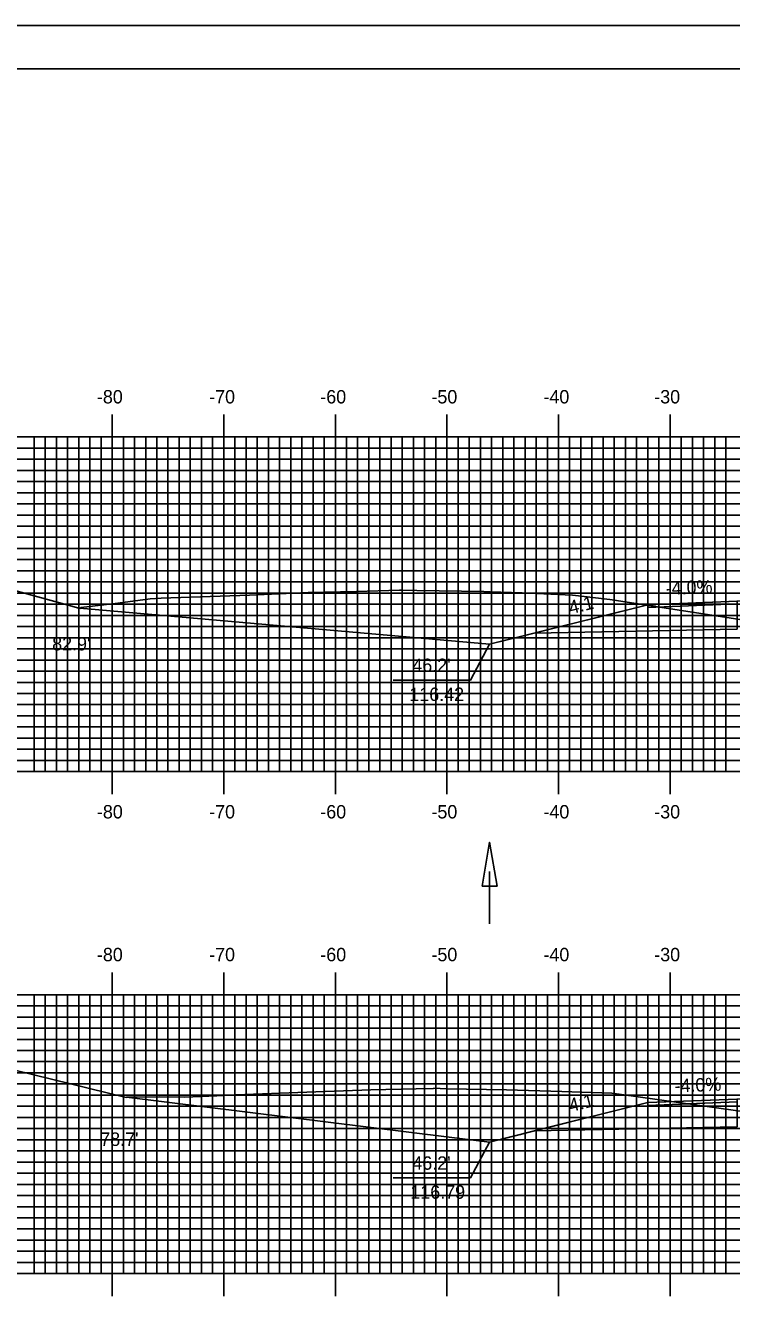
# Model space of a CAD drawing. Extents: x 854287 to 854631, y 366605 to 366825.
# Drawn here: x 854365.3 to 854428.5, y 366710.6 to 366824.9 of the extents above; entities that cross this region are included whole.
import ezdxf

# ---------------------------------------------------------------- set-up
doc = ezdxf.new("R2010")
doc.units = 0
for name, color, linetype in [('ANNOTATION', 7, 'Continuous'), ('BORDER', 7, 'Continuous'), ('D_Drainage_Ditch_Line', 7, 'Continuous'), ('D_Drainage_Underdrain', 7, 'Continuous'), ('D_Roadway_Centerline', 7, 'Continuous'), ('D_Roadway_Edge_Shoulder', 7, 'Continuous'), ('D_Roadway_SlopeLines', 7, 'Continuous'), ('D_Roadway_SubGrade', 7, 'Continuous'), ('D_Text_Standard', 7, 'Continuous'), ('H_V ANNOTATION', 7, 'Continuous'), ('M_Roadway_Centerline', 7, 'Continuous'), ('MAJOR', 7, 'Continuous'), ('MINOR', 7, 'Continuous'), ('PLOT BOUNDARY', 7, 'Continuous'), ('S_Roadway_Centerline', 7, 'Continuous')]:
    doc.layers.add(name, color=color, linetype=linetype)

msp = doc.modelspace()

# ---------------------------------------------------------------- linework, layer by layer
at = {"layer": 'ANNOTATION'}
for points in [[(854410.87, 366770.48), (854406.87, 366769.48), (854370.14, 366772.7)], [(854398.21, 366766.27), (854405.14, 366766.27), (854406.87, 366769.48)], [(854398.21, 366721.64), (854405.14, 366721.64), (854406.87, 366724.85)]]:
    msp.add_lwpolyline(points, dxfattribs=at)
at = {"layer": 'BORDER'}
msp.add_lwpolyline([(854303.44, 366611.06), (854623.44, 366611.06), (854623.44, 366821.06), (854303.44, 366821.06)], close=True, dxfattribs=at)
at = {"layer": 'D_Drainage_Ditch_Line'}
msp.add_line((854406.87, 366749.11), (854406.87, 366744.41), dxfattribs=at)
msp.add_lwpolyline([(854407.53, 366747.8), (854406.21, 366747.8), (854406.87, 366751.73)], close=True, dxfattribs=at)
at = {"layer": 'D_Drainage_Underdrain'}
msp.add_lwpolyline([(854410.87, 366725.85), (854406.87, 366724.85), (854374.32, 366728.87)], dxfattribs=at)
at = {"layer": 'D_Roadway_Centerline'}
for points in [[(854370.14, 366772.7), (854370.15, 366772.7), (854406.87, 366769.48), (854410.14, 366770.29), (854410.15, 366770.29), (854421.04, 366773.02), (854421.05, 366773.02), (854423.89, 366773.13), (854429.04, 366773.34), (854429.04, 366773.34), (854441.04, 366773.58), (854441.04, 366773.58), (854449.37, 366773.75), (854453.04, 366773.82), (854454.84, 366773.75), (854457.04, 366773.66), (854463.48, 366772.96), (854463.48, 366772.96)], [(854374.32, 366728.87), (854406.87, 366724.85), (854409.62, 366725.54), (854410.14, 366725.67), (854421.04, 366728.39), (854422.63, 366728.46), (854429.04, 366728.71), (854429.04, 366728.71), (854429.05, 366728.71), (854441.04, 366728.95), (854447.09, 366729.07), (854453.04, 366729.19), (854453.58, 366729.17), (854457.04, 366729.03), (854464.66, 366728.25)]]:
    msp.add_lwpolyline(points, dxfattribs=at)
at = {"layer": 'D_Roadway_Edge_Shoulder'}
for points in [[(854429.04, 366773.34), (854421.04, 366773.02), (854421.04, 366772.77), (854429.04, 366773.09)], [(854429.04, 366728.71), (854421.04, 366728.39), (854421.04, 366728.14), (854429.04, 366728.46)]]:
    msp.add_lwpolyline(points, close=True, dxfattribs=at)
at = {"layer": 'D_Roadway_SlopeLines'}
for p, q in [((854406.87, 366769.48), (854370.14, 366772.7)), ((854421.04, 366773.02), (854406.87, 366769.48)), ((854406.87, 366724.85), (854374.32, 366728.87)), ((854421.04, 366728.39), (854406.87, 366724.85))]:
    msp.add_line(p, q, dxfattribs=at)
at = {"layer": 'D_Roadway_SubGrade'}
for points in [[(854429.04, 366772.67), (854429.04, 366773.09), (854421.04, 366772.77), (854421.04, 366773.02), (854410.87, 366770.48), (854429.04, 366770.84)], [(854429.04, 366728.05), (854429.04, 366728.46), (854421.04, 366728.14), (854421.04, 366728.39), (854410.87, 366725.85), (854429.04, 366726.21)]]:
    msp.add_lwpolyline(points, close=True, dxfattribs=at)
at = {"layer": 'MAJOR'}
for p, q in [((854373.04, 366790.06), (854373.04, 366788.06)), ((854383.04, 366790.06), (854383.04, 366788.06)), ((854393.04, 366790.06), (854393.04, 366788.06)), ((854403.04, 366790.06), (854403.04, 366788.06)), ((854413.04, 366790.06), (854413.04, 366788.06)), ((854423.04, 366790.06), (854423.04, 366788.06)), ((854313.04, 366788.06), (854593.04, 366788.06)), ((854313.04, 366788.06), (854593.04, 366788.06)), ((854373.04, 366758.06), (854373.04, 366788.06)), ((854383.04, 366758.06), (854383.04, 366788.06)), ((854393.04, 366758.06), (854393.04, 366788.06)), ((854403.04, 366758.06), (854403.04, 366788.06)), ((854413.04, 366758.06), (854413.04, 366788.06)), ((854423.04, 366758.06), (854423.04, 366788.06)), ((854313.04, 366783.06), (854593.04, 366783.06)), ((854313.04, 366778.06), (854593.04, 366778.06)), ((854313.04, 366773.06), (854593.04, 366773.06)), ((854313.04, 366768.06), (854593.04, 366768.06)), ((854313.04, 366763.06), (854593.04, 366763.06)), ((854313.04, 366758.06), (854593.04, 366758.06)), ((854313.04, 366758.06), (854593.04, 366758.06)), ((854373.04, 366756.05), (854373.04, 366758.06)), ((854383.04, 366756.05), (854383.04, 366758.06)), ((854393.04, 366756.05), (854393.04, 366758.06)), ((854403.04, 366756.05), (854403.04, 366758.06)), ((854413.04, 366756.05), (854413.04, 366758.06)), ((854423.04, 366756.05), (854423.04, 366758.06)), ((854373.04, 366740.06), (854373.04, 366738.06)), ((854383.04, 366740.06), (854383.04, 366738.06)), ((854393.04, 366740.06), (854393.04, 366738.06)), ((854403.04, 366740.06), (854403.04, 366738.06)), ((854413.04, 366740.06), (854413.04, 366738.06)), ((854423.04, 366740.06), (854423.04, 366738.06)), ((854313.04, 366738.06), (854593.04, 366738.06)), ((854313.04, 366738.06), (854593.04, 366738.06)), ((854373.04, 366713.06), (854373.04, 366738.06)), ((854383.04, 366713.06), (854383.04, 366738.06)), ((854393.04, 366713.06), (854393.04, 366738.06)), ((854403.04, 366713.06), (854403.04, 366738.06)), ((854413.04, 366713.06), (854413.04, 366738.06)), ((854423.04, 366713.06), (854423.04, 366738.06)), ((854313.04, 366733.06), (854593.04, 366733.06)), ((854313.04, 366728.06), (854593.04, 366728.06)), ((854313.04, 366723.06), (854593.04, 366723.06)), ((854313.04, 366718.06), (854593.04, 366718.06)), ((854313.04, 366713.06), (854593.04, 366713.06)), ((854313.04, 366713.06), (854593.04, 366713.06)), ((854373.04, 366711.05), (854373.04, 366713.06)), ((854383.04, 366711.05), (854383.04, 366713.06)), ((854393.04, 366711.05), (854393.04, 366713.06)), ((854403.04, 366711.05), (854403.04, 366713.06)), ((854413.04, 366711.05), (854413.04, 366713.06)), ((854423.04, 366711.05), (854423.04, 366713.06))]:
    msp.add_line(p, q, dxfattribs=at)
at = {"layer": 'MINOR'}
for p, q in [((854366.04, 366758.06), (854366.04, 366788.06)), ((854367.04, 366758.06), (854367.04, 366788.06)), ((854368.04, 366758.06), (854368.04, 366788.06)), ((854369.04, 366758.06), (854369.04, 366788.06)), ((854370.04, 366758.06), (854370.04, 366788.06)), ((854371.04, 366758.06), (854371.04, 366788.06)), ((854372.04, 366758.06), (854372.04, 366788.06)), ((854374.04, 366758.06), (854374.04, 366788.06)), ((854375.04, 366758.06), (854375.04, 366788.06)), ((854376.04, 366758.06), (854376.04, 366788.06)), ((854377.04, 366758.06), (854377.04, 366788.06)), ((854378.04, 366758.06), (854378.04, 366788.06)), ((854379.04, 366758.06), (854379.04, 366788.06)), ((854380.04, 366758.06), (854380.04, 366788.06)), ((854381.04, 366758.06), (854381.04, 366788.06)), ((854382.04, 366758.06), (854382.04, 366788.06)), ((854384.04, 366758.06), (854384.04, 366788.06)), ((854385.04, 366758.06), (854385.04, 366788.06)), ((854386.04, 366758.06), (854386.04, 366788.06)), ((854387.04, 366758.06), (854387.04, 366788.06)), ((854388.04, 366758.06), (854388.04, 366788.06)), ((854389.04, 366758.06), (854389.04, 366788.06)), ((854390.04, 366758.06), (854390.04, 366788.06)), ((854391.04, 366758.06), (854391.04, 366788.06)), ((854392.04, 366758.06), (854392.04, 366788.06)), ((854394.04, 366758.06), (854394.04, 366788.06)), ((854395.04, 366758.06), (854395.04, 366788.06)), ((854396.04, 366758.06), (854396.04, 366788.06)), ((854397.04, 366758.06), (854397.04, 366788.06)), ((854398.04, 366758.06), (854398.04, 366788.06)), ((854399.04, 366758.06), (854399.04, 366788.06)), ((854400.04, 366758.06), (854400.04, 366788.06)), ((854401.04, 366758.06), (854401.04, 366788.06)), ((854402.04, 366758.06), (854402.04, 366788.06)), ((854404.04, 366758.06), (854404.04, 366788.06)), ((854405.04, 366758.06), (854405.04, 366788.06)), ((854406.04, 366758.06), (854406.04, 366788.06)), ((854407.04, 366758.06), (854407.04, 366788.06)), ((854408.04, 366758.06), (854408.04, 366788.06)), ((854409.04, 366758.06), (854409.04, 366788.06)), ((854410.04, 366758.06), (854410.04, 366788.06)), ((854411.04, 366758.06), (854411.04, 366788.06)), ((854412.04, 366758.06), (854412.04, 366788.06)), ((854414.04, 366758.06), (854414.04, 366788.06)), ((854415.04, 366758.06), (854415.04, 366788.06)), ((854416.04, 366758.06), (854416.04, 366788.06)), ((854417.04, 366758.06), (854417.04, 366788.06)), ((854418.04, 366758.06), (854418.04, 366788.06)), ((854419.04, 366758.06), (854419.04, 366788.06)), ((854420.04, 366758.06), (854420.04, 366788.06)), ((854421.04, 366758.06), (854421.04, 366788.06)), ((854422.04, 366758.06), (854422.04, 366788.06)), ((854424.04, 366758.06), (854424.04, 366788.06)), ((854425.04, 366758.06), (854425.04, 366788.06)), ((854426.04, 366758.06), (854426.04, 366788.06)), ((854427.04, 366758.06), (854427.04, 366788.06)), ((854428.04, 366758.06), (854428.04, 366788.06)), ((854313.04, 366787.06), (854593.04, 366787.06)), ((854313.04, 366786.06), (854593.04, 366786.06)), ((854313.04, 366785.06), (854593.04, 366785.06)), ((854313.04, 366784.06), (854593.04, 366784.06)), ((854313.04, 366782.06), (854593.04, 366782.06)), ((854313.04, 366781.06), (854593.04, 366781.06)), ((854313.04, 366780.06), (854593.04, 366780.06)), ((854313.04, 366779.06), (854593.04, 366779.06)), ((854313.04, 366777.06), (854593.04, 366777.06)), ((854313.04, 366776.06), (854593.04, 366776.06)), ((854313.04, 366775.06), (854593.04, 366775.06)), ((854313.04, 366774.06), (854593.04, 366774.06)), ((854313.04, 366772.06), (854593.04, 366772.06)), ((854313.04, 366771.06), (854593.04, 366771.06)), ((854313.04, 366770.06), (854593.04, 366770.06)), ((854313.04, 366769.06), (854593.04, 366769.06)), ((854313.04, 366767.06), (854593.04, 366767.06)), ((854313.04, 366766.06), (854593.04, 366766.06)), ((854313.04, 366765.06), (854593.04, 366765.06)), ((854313.04, 366764.06), (854593.04, 366764.06)), ((854313.04, 366762.06), (854593.04, 366762.06)), ((854313.04, 366761.06), (854593.04, 366761.06)), ((854313.04, 366760.06), (854593.04, 366760.06)), ((854313.04, 366759.06), (854593.04, 366759.06)), ((854313.04, 366737.06), (854593.04, 366737.06)), ((854366.04, 366713.06), (854366.04, 366738.06)), ((854367.04, 366713.06), (854367.04, 366738.06)), ((854368.04, 366713.06), (854368.04, 366738.06)), ((854369.04, 366713.06), (854369.04, 366738.06)), ((854370.04, 366713.06), (854370.04, 366738.06)), ((854371.04, 366713.06), (854371.04, 366738.06)), ((854372.04, 366713.06), (854372.04, 366738.06)), ((854374.04, 366713.06), (854374.04, 366738.06)), ((854375.04, 366713.06), (854375.04, 366738.06)), ((854376.04, 366713.06), (854376.04, 366738.06)), ((854377.04, 366713.06), (854377.04, 366738.06)), ((854378.04, 366713.06), (854378.04, 366738.06)), ((854379.04, 366713.06), (854379.04, 366738.06)), ((854380.04, 366713.06), (854380.04, 366738.06)), ((854381.04, 366713.06), (854381.04, 366738.06)), ((854382.04, 366713.06), (854382.04, 366738.06)), ((854384.04, 366713.06), (854384.04, 366738.06)), ((854385.04, 366713.06), (854385.04, 366738.06)), ((854386.04, 366713.06), (854386.04, 366738.06)), ((854387.04, 366713.06), (854387.04, 366738.06)), ((854388.04, 366713.06), (854388.04, 366738.06)), ((854389.04, 366713.06), (854389.04, 366738.06)), ((854390.04, 366713.06), (854390.04, 366738.06)), ((854391.04, 366713.06), (854391.04, 366738.06)), ((854392.04, 366713.06), (854392.04, 366738.06)), ((854394.04, 366713.06), (854394.04, 366738.06)), ((854395.04, 366713.06), (854395.04, 366738.06)), ((854396.04, 366713.06), (854396.04, 366738.06)), ((854397.04, 366713.06), (854397.04, 366738.06)), ((854398.04, 366713.06), (854398.04, 366738.06)), ((854399.04, 366713.06), (854399.04, 366738.06)), ((854400.04, 366713.06), (854400.04, 366738.06)), ((854401.04, 366713.06), (854401.04, 366738.06)), ((854402.04, 366713.06), (854402.04, 366738.06)), ((854404.04, 366713.06), (854404.04, 366738.06)), ((854405.04, 366713.06), (854405.04, 366738.06)), ((854406.04, 366713.06), (854406.04, 366738.06)), ((854407.04, 366713.06), (854407.04, 366738.06)), ((854408.04, 366713.06), (854408.04, 366738.06)), ((854409.04, 366713.06), (854409.04, 366738.06)), ((854410.04, 366713.06), (854410.04, 366738.06)), ((854411.04, 366713.06), (854411.04, 366738.06)), ((854412.04, 366713.06), (854412.04, 366738.06)), ((854414.04, 366713.06), (854414.04, 366738.06)), ((854415.04, 366713.06), (854415.04, 366738.06)), ((854416.04, 366713.06), (854416.04, 366738.06)), ((854417.04, 366713.06), (854417.04, 366738.06)), ((854418.04, 366713.06), (854418.04, 366738.06)), ((854419.04, 366713.06), (854419.04, 366738.06)), ((854420.04, 366713.06), (854420.04, 366738.06)), ((854421.04, 366713.06), (854421.04, 366738.06)), ((854422.04, 366713.06), (854422.04, 366738.06)), ((854424.04, 366713.06), (854424.04, 366738.06)), ((854425.04, 366713.06), (854425.04, 366738.06)), ((854426.04, 366713.06), (854426.04, 366738.06)), ((854427.04, 366713.06), (854427.04, 366738.06)), ((854428.04, 366713.06), (854428.04, 366738.06)), ((854313.04, 366736.06), (854593.04, 366736.06)), ((854313.04, 366735.06), (854593.04, 366735.06)), ((854313.04, 366734.06), (854593.04, 366734.06)), ((854313.04, 366732.06), (854593.04, 366732.06)), ((854313.04, 366731.06), (854593.04, 366731.06)), ((854313.04, 366730.06), (854593.04, 366730.06)), ((854313.04, 366729.06), (854593.04, 366729.06)), ((854313.04, 366727.06), (854593.04, 366727.06)), ((854313.04, 366726.06), (854593.04, 366726.06)), ((854313.04, 366725.06), (854593.04, 366725.06)), ((854313.04, 366724.06), (854593.04, 366724.06)), ((854313.04, 366722.06), (854593.04, 366722.06)), ((854313.04, 366721.06), (854593.04, 366721.06)), ((854313.04, 366720.06), (854593.04, 366720.06)), ((854313.04, 366719.06), (854593.04, 366719.06)), ((854313.04, 366717.06), (854593.04, 366717.06)), ((854313.04, 366716.06), (854593.04, 366716.06)), ((854313.04, 366715.06), (854593.04, 366715.06)), ((854313.04, 366714.06), (854593.04, 366714.06))]:
    msp.add_line(p, q, dxfattribs=at)
at = {"layer": 'PLOT BOUNDARY'}
msp.add_lwpolyline([(854287.26, 366604.94), (854627.26, 366604.94), (854627.26, 366824.94), (854287.26, 366824.94)], close=True, dxfattribs=at)
at = {"layer": 'S_Roadway_Centerline'}
for points in [[(854355.35, 366776.74), (854369.43, 366772.89), (854370.13, 366772.69), (854370.27, 366772.76), (854373.53, 366773.16), (854376.45, 366773.56), (854377.43, 366773.6), (854385.36, 366773.88), (854390.61, 366774.12), (854394.95, 366774.21), (854398.8, 366774.31), (854398.93, 366774.33), (854400.35, 366774.29), (854406.34, 366774.2), (854406.91, 366774.18), (854409.78, 366774.07), (854414.28, 366773.87), (854414.82, 366773.83), (854417.65, 366773.49), (854429.9, 366771.61)], [(854364.31, 366731.31), (854374.29, 366728.86), (854374.32, 366728.87), (854377.26, 366728.9), (854379.54, 366728.88), (854382.42, 366729.01), (854384.11, 366729.09), (854390.47, 366729.31), (854396.22, 366729.54), (854400.28, 366729.63), (854401.84, 366729.66), (854401.86, 366729.67), (854403, 366729.63), (854408.38, 366729.52), (854413.34, 366729.38), (854417.83, 366729.24), (854419.96, 366728.95), (854423.8, 366728.39), (854433.58, 366727.02)]]:
    msp.add_lwpolyline(points, dxfattribs=at)

# ---------------------------------------------------------------- texts
at = {"layer": 'ANNOTATION'}
for s, rotation, p in [('-4.0%', 2.2908, (854422.67, 366773.89)), ('4:1', 14.0381, (854414.13, 366772.15)), ("46.2' ", 360, (854399.94, 366766.99)), ('116.42', 360, (854399.67, 366764.39)), ('-4.0%', 2.2908, (854423.46, 366729.29)), ('4:1', 14.0332, (854414.13, 366727.53)), ("46.2' ", 360, (854399.94, 366722.37)), ('116.79', 360, (854399.76, 366719.77))]:
    msp.add_text(s, height=1.2, rotation=rotation, dxfattribs=at).set_placement(p)
at = {"layer": 'D_Text_Standard'}
for s, p in [("82.9'", (854367.66, 366768.92)), ("78.7'", (854371.97, 366724.51))]:
    msp.add_text(s, height=1.2, dxfattribs=at).set_placement(p)
at = {"layer": 'H_V ANNOTATION'}
for s, p in [('-80', (854371.67, 366791.06)), ('-70', (854381.73, 366791.06)), ('-60', (854391.69, 366791.06)), ('-50', (854401.65, 366791.06)), ('-40', (854411.69, 366791.06)), ('-30', (854421.62, 366791.06)), ('-80', (854371.67, 366753.86)), ('-70', (854381.73, 366753.86)), ('-60', (854391.69, 366753.86)), ('-50', (854401.65, 366753.86)), ('-40', (854411.69, 366753.86)), ('-30', (854421.62, 366753.86)), ('-80', (854371.67, 366741.06)), ('-70', (854381.73, 366741.06)), ('-60', (854391.69, 366741.06)), ('-50', (854401.65, 366741.06)), ('-40', (854411.69, 366741.06)), ('-30', (854421.62, 366741.06))]:
    msp.add_text(s, height=1.2, dxfattribs=at).set_placement(p)
at = {"layer": 'M_Roadway_Centerline'}
for s, p in [('C', (854398.92, 366774.33)), ('L', (854398.93, 366774.32)), ('C', (854401.86, 366729.67)), ('L', (854401.86, 366729.66))]:
    msp.add_text(s, height=0.0146, dxfattribs=at).set_placement(p)

doc.saveas('drawing.dxf')
